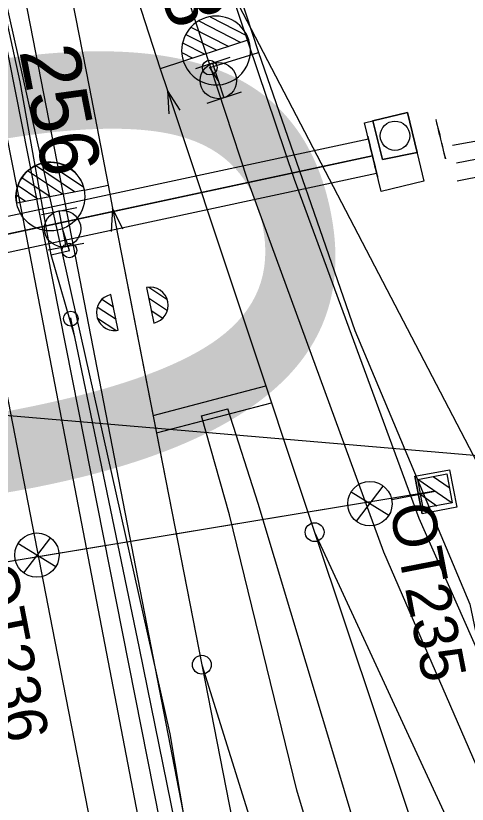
# Model space of a CAD drawing. Extents: x -545846 to -545044, y -1122650 to -1119108.
# Drawn here: x -545638.82 to -545623.48, y -1119592.1 to -1119565.28 of the extents above; entities that cross this region are included whole.
import ezdxf

# ---------------------------------------------------------------- set-up
doc = ezdxf.new("R2010")
doc.units = 0
for name, color, linetype in [('osvětlené plochy-hodnota-obrys', 7, 'Continuous'), ('Vrstva 1 - Koleje', 7, 'Continuous'), ('Vrstva 11 - Trakce', 7, 'Continuous'), ('Vrstva 12 - Trakce zaklady', 7, 'Continuous'), ('Vrstva 19', 7, 'Continuous'), ('Vrstva 2 - Vyhybky', 7, 'Continuous'), ('Vrstva 25', 7, 'Continuous'), ('Vrstva 27', 7, 'Continuous'), ('Vrstva 28 - zabzar', 7, 'Continuous'), ('Vrstva 3 - Lisy - Pocitaci body', 7, 'Continuous'), ('Vrstva 4 - Teren - stezky - prechody - plochy', 7, 'Continuous'), ('Vrstva 43', 7, 'Continuous'), ('Vrstva 44', 7, 'Continuous'), ('Vrstva 47', 7, 'Continuous'), ('Vrstva 63', 7, 'Continuous'), ('Vrstva 7 - Namezniky-vystroj', 7, 'Continuous')]:
    doc.layers.add(name, color=color, linetype=linetype)

msp = doc.modelspace()

# ---------------------------------------------------------------- linework, layer by layer
at = {"layer": 'osvětlené plochy-hodnota-obrys'}
msp.add_line((-545562.16, -1119697.713), (-545631.883, -1119563.683), dxfattribs=at)
msp.add_lwpolyline([(-545716.386, -1119223.717), (-545705.994, -1119221.66), (-545669.439, -1119408.759), (-545659.4, -1119462.635), (-545647.69, -1119521.347), (-545640.519, -1119558.729), (-545633.585, -1119589.698), (-545629.517, -1119613.814), (-545623.042, -1119645.057), (-545619.034, -1119667.556), (-545607.519, -1119727.517)], dxfattribs=at)
at = {"layer": 'Vrstva 1 - Koleje'}
for points in [[(-545653.037, -1119506.841), (-545652.888, -1119507.607), (-545652.099, -1119511.657), (-545649.059, -1119527.252), (-545644.851, -1119548.835), (-545643.914, -1119553.655), (-545642.404, -1119561.39), (-545639.909, -1119574.181), (-545637.584, -1119586.095), (-545635.82, -1119595.156), (-545633.965, -1119604.658), (-545632.137, -1119614.029), (-545631.264, -1119618.51), (-545629.612, -1119626.967), (-545629.361, -1119628.256), (-545628.203, -1119634.204), (-545626.651, -1119642.2), (-545624.573, -1119652.836), (-545622.753, -1119662.157), (-545621.579, -1119668.177), (-545619.497, -1119678.862), (-545617.408, -1119689.578), (-545615.292, -1119700.416), (-545613.256, -1119710.876)], [(-545643.734, -1119529.746), (-545643.581, -1119530.531), (-545640.551, -1119546.054), (-545635.586, -1119561.921), (-545633.918, -1119567.079)], [(-545643.734, -1119529.746), (-545643.581, -1119530.531), (-545642.913, -1119533.951), (-545640.551, -1119546.054), (-545637.367, -1119562.371), (-545636.332, -1119567.693), (-545635.682, -1119571.044)], [(-545633.918, -1119567.079), (-545633.672, -1119567.819), (-545628.667, -1119582.843), (-545621.718, -1119597.894), (-545620.45, -1119600.642), (-545619.123, -1119603.519)], [(-545633.918, -1119567.079), (-545633.672, -1119567.819), (-545628.667, -1119582.843), (-545623.418, -1119598.57), (-545620.367, -1119607.688), (-545618.295, -1119613.58)], [(-545635.682, -1119571.044), (-545635.531, -1119571.819), (-545632.499, -1119587.351), (-545627.516, -1119603.306)], [(-545635.682, -1119571.044), (-545635.531, -1119571.819), (-545634.862, -1119575.245), (-545632.499, -1119587.351), (-545629.31, -1119603.689), (-545628.19, -1119609.432), (-545627.412, -1119613.414), (-545625.512, -1119623.176), (-545623.669, -1119632.632), (-545622.964, -1119636.244), (-545621.873, -1119641.833), (-545619.406, -1119654.493), (-545617.375, -1119664.914), (-545615.537, -1119674.339), (-545613.73, -1119683.606), (-545613.194, -1119686.362), (-545611.288, -1119696.135), (-545609.289, -1119706.39), (-545607.258, -1119716.828)]]:
    msp.add_lwpolyline(points, dxfattribs=at)
at = {"layer": 'Vrstva 11 - Trakce'}
for p, q in [((-545624.636, -1119580.948), (-545624.091, -1119581.32)), ((-545625.157, -1119581.045), (-545623.993, -1119581.841)), ((-545624.576, -1119581.445), (-545651.228, -1119585.868)), ((-545625.062, -1119581.564), (-545624.51, -1119581.941))]:
    msp.add_line(p, q, dxfattribs=at)
msp.add_lwpolyline([(-545624.177, -1119580.861), (-545623.992, -1119581.844), (-545624.975, -1119582.029), (-545625.16, -1119581.046)], close=True, dxfattribs=at)
at = {"layer": 'Vrstva 12 - Trakce zaklady'}
for p, q in [((-545625.258, -1119580.939), (-545624.079, -1119580.717)), ((-545623.839, -1119581.994), (-545625.018, -1119582.216))]:
    msp.add_line(p, q, dxfattribs=at)
for points in [[(-545625.018, -1119582.216), (-545625.258, -1119580.939), (-545624.079, -1119580.717), (-545623.839, -1119581.994), (-545625.018, -1119582.216)], [(-545624.079, -1119580.717), (-545624.079, -1119580.717), (-545623.839, -1119581.994), (-545623.839, -1119581.994)], [(-545625.258, -1119580.939), (-545625.258, -1119580.939), (-545625.018, -1119582.216), (-545625.018, -1119582.216)]]:
    msp.add_lwpolyline(points, dxfattribs=at)
at = {"layer": 'Vrstva 19'}
for p, q in [((-545493.78, -1119544.934), (-545623.981, -1119569.695)), ((-545623.845, -1119570.275), (-545493.722, -1119545.549)), ((-545493.532, -1119546.146), (-545623.825, -1119570.899))]:
    msp.add_line(p, q, dxfattribs=at)
for points in [[(-545664.878, -1119577.632), (-545626.84, -1119569.462)], [(-545664.746, -1119578.217), (-545626.701, -1119570.045)], [(-545626.702, -1119570.04), (-545663.566, -1119577.951)], [(-545664.614, -1119578.802), (-545626.561, -1119570.628)]]:
    msp.add_lwpolyline(points, dxfattribs=at)
for centre, major_axis, ratio, start_param, end_param in [((-545624.383, -1119569.48), (-0.162, 0.672), 0.01248, 4.711186, 7.847666), ((-545626.696, -1119570.067), (-0.165, 0.695), 0.00013, 4.750534, 7.822978), ((-545624.383, -1119569.477), (0.162, -0.672), 0.01248, 4.711186, 7.847666), ((-545626.696, -1119570.067), (-0.166, 0.694), 0.000133, 1.539607, 4.75072)]:
    msp.add_ellipse(centre, major_axis=major_axis, ratio=ratio, start_param=start_param, end_param=end_param, dxfattribs=at)
at = {"layer": 'Vrstva 2 - Vyhybky'}
for p, q in [((-545632.607, -1119565.454), (-545631.171, -1119566.189)), ((-545632.222, -1119565.31), (-545630.96, -1119565.955)), ((-545632.868, -1119565.663), (-545631.58, -1119566.321)), ((-545633.046, -1119565.913), (-545631.99, -1119566.453)), ((-545633.153, -1119566.199), (-545632.399, -1119566.585)), ((-545630.9, -1119566.101), (-545633.128, -1119566.821)), ((-545630.9, -1119566.1), (-545630.9, -1119566.101)), ((-545633.181, -1119566.527), (-545632.808, -1119566.717)), ((-545633.128, -1119566.821), (-545633.918, -1119567.079)), ((-545636.513, -1119571.117), (-545637.773, -1119570.268)), ((-545637.239, -1119571.35), (-545638.418, -1119570.557)), ((-545636.823, -1119571.269), (-545638.149, -1119570.376)), ((-545637.656, -1119571.431), (-545638.615, -1119570.786)), ((-545638.073, -1119571.512), (-545638.746, -1119571.059)), ((-545636.489, -1119571.204), (-545635.682, -1119571.044)), ((-545636.489, -1119571.204), (-545638.788, -1119571.652)), ((-545636.49, -1119571.203), (-545636.489, -1119571.204)), ((-545638.49, -1119571.594), (-545638.806, -1119571.381))]:
    msp.add_line(p, q, dxfattribs=at)
for points in [[(-545633.918, -1119567.079), (-545633.672, -1119567.819), (-545628.667, -1119582.843), (-545623.418, -1119598.57)], [(-545633.231, -1119568.487), (-545633.672, -1119567.819), (-545633.624, -1119568.618)], [(-545635.682, -1119571.044), (-545635.531, -1119571.819), (-545632.499, -1119587.351), (-545629.31, -1119603.689)], [(-545635.18, -1119572.538), (-545635.531, -1119571.819), (-545635.586, -1119572.617)], [(-545628.667, -1119582.843), (-545621.718, -1119597.894)], [(-545632.499, -1119587.351), (-545627.516, -1119603.306)]]:
    msp.add_lwpolyline(points, dxfattribs=at)
for centre, radius in [((-545637.645, -1119571.428), 1.17), ((-545628.667, -1119582.843), 0.32), ((-545632.499, -1119587.351), 0.32)]:
    msp.add_circle(centre, radius, dxfattribs=at)
for centre, radius, start, end in [((-545632.014, -1119566.461), 1.171, 17.9478, 197.9086), ((-545632.015, -1119566.462), 1.17, 197.8583, 18.3278), ((-545637.639, -1119571.428), 1.171, 11.0643, 191.0252)]:
    msp.add_arc(centre, radius, start, end, dxfattribs=at)
at = {"layer": 'Vrstva 25'}
for p, q in [((-545627.248, -1119582.472), (-545626.335, -1119581.273)), ((-545627.427, -1119581.473), (-545626.143, -1119582.264)), ((-545626.048, -1119581.732), (-545624.576, -1119581.445)), ((-545637.645, -1119583.025), (-545638.558, -1119584.224)), ((-545637.466, -1119584.025), (-545638.75, -1119583.233))]:
    msp.add_line(p, q, dxfattribs=at)
msp.add_lwpolyline([(-545624.576, -1119581.445), (-545650.585, -1119585.754)], dxfattribs=at)
for centre in [(-545626.789, -1119581.874), (-545638.104, -1119583.623)]:
    msp.add_circle(centre, 0.754, dxfattribs=at)
at = {"layer": 'Vrstva 27'}
for p, q in [((-545632.238, -1119567.016), (-545632.222, -1119567.064)), ((-545636.995, -1119573.285), (-545637.005, -1119573.235)), ((-545636.945, -1119575.605), (-545636.955, -1119575.555))]:
    msp.add_line(p, q, dxfattribs=at)
for centre in [(-545632.23, -1119567.04), (-545637, -1119573.26), (-545636.95, -1119575.58)]:
    msp.add_circle(centre, 0.25, dxfattribs=at)
at = {"layer": 'Vrstva 28 - zabzar'}
msp.add_line((-545636.82, -1119576.2), (-545636.95, -1119575.58), dxfattribs=at)
for points in [[(-545629.8, -1119612.08), (-545631.93, -1119600), (-545634.62, -1119586.79), (-545636.82, -1119576.2), (-545637.62, -1119573.41), (-545638.67, -1119567.53), (-545639.49, -1119563.82), (-545639.85, -1119560.18), (-545641.01, -1119554.98), (-545644.07, -1119538.51), (-545646.66, -1119527.22), (-545647.144, -1119525.532), (-545647.46, -1119524.27), (-545648.47, -1119517.64), (-545649.03, -1119512.55), (-545649.84, -1119510.97), (-545650.5, -1119507.69), (-545650.68, -1119506.85), (-545651.64, -1119501.97), (-545654.86, -1119485.39)], [(-545642.06, -1119524.64), (-545640.63, -1119530.69), (-545639.91, -1119533.39), (-545637.75, -1119542.87), (-545634.65, -1119553.48), (-545633.29, -1119558.34), (-545631.9, -1119562.47), (-545630.58, -1119566.53), (-545627.3, -1119575.98), (-545623.39, -1119585.29), (-545622.71, -1119588.53), (-545617.63, -1119597.85), (-545616.86, -1119599.1), (-545615.46, -1119602.1), (-545610.32, -1119612.67), (-545606.39, -1119619.85), (-545601.98, -1119627.31), (-545600.79, -1119629.4), (-545602.25, -1119630.29), (-545602.73, -1119630.37), (-545602.6, -1119631.07)], [(-545631.94, -1119567.48), (-545632.23, -1119567.04), (-545630.58, -1119566.53)], [(-545637.62, -1119573.41), (-545637, -1119573.26), (-545637.23, -1119572.52)]]:
    msp.add_lwpolyline(points, dxfattribs=at)
at = {"layer": 'Vrstva 3 - Lisy - Pocitaci body'}
for p, q in [((-545631.548, -1119566.702), (-545632.718, -1119567.088)), ((-545632.133, -1119566.895), (-545631.747, -1119568.065)), ((-545631.162, -1119567.872), (-545632.332, -1119568.258)), ((-545637.952, -1119572.033), (-545636.743, -1119571.798)), ((-545637.112, -1119573.125), (-545637.348, -1119571.915)), ((-545637.717, -1119573.242), (-545636.508, -1119573.007)), ((-545634.38, -1119574.521), (-545634.135, -1119575.728)), ((-545634.297, -1119574.51), (-545633.684, -1119574.918)), ((-545635.344, -1119575.969), (-545635.589, -1119574.762)), ((-545635.589, -1119574.762), (-545635.589, -1119574.762)), ((-545635.503, -1119575.186), (-545635.899, -1119574.928)), ((-545634.308, -1119574.876), (-545633.669, -1119575.299)), ((-545635.416, -1119575.614), (-545636.055, -1119575.191)), ((-545634.221, -1119575.304), (-545633.825, -1119575.562)), ((-545635.427, -1119575.98), (-545636.04, -1119575.572)), ((-545634.135, -1119575.728), (-545634.135, -1119575.728))]:
    msp.add_line(p, q, dxfattribs=at)
for centre in [(-545631.939, -1119567.482), (-545637.231, -1119572.518)]:
    msp.add_circle(centre, 0.616, dxfattribs=at)
for centre, start, end in [((-545634.257, -1119575.125), 11.4785, 101.4785), ((-545635.467, -1119575.365), 101.4785, 191.4785), ((-545634.257, -1119575.125), 281.4785, 11.4785), ((-545635.467, -1119575.365), 191.4785, 281.4785)]:
    msp.add_arc(centre, 0.616, start, end, dxfattribs=at)
at = {"layer": 'Vrstva 4 - Teren - stezky - prechody - plochy'}
for points in [[(-545658.883, -1119493.553), (-545657.157, -1119493.293), (-545652.405, -1119492.3), (-545652.635, -1119491.288), (-545650.366, -1119490.81), (-545647.977, -1119490.635), (-545647.021, -1119490.553), (-545646.397, -1119493.557), (-545647.333, -1119493.819), (-545645.82, -1119500.741), (-545643.399, -1119514.848), (-545641.375, -1119525.057), (-545641.371, -1119525.071), (-545641.178, -1119529.067), (-545640.191, -1119530.535), (-545638.605, -1119538.618), (-545635.76, -1119550.157), (-545633.177, -1119559.269), (-545632.795, -1119560.648), (-545629.367, -1119570.838), (-545625.13, -1119582.366), (-545619.179, -1119595.829), (-545614.308, -1119606.243)], [(-545647.977, -1119490.635), (-545647.021, -1119490.553), (-545646.397, -1119493.557), (-545647.333, -1119493.819), (-545645.82, -1119500.741), (-545643.399, -1119514.848), (-545641.375, -1119525.057), (-545641.371, -1119525.071), (-545641.178, -1119529.067), (-545640.191, -1119530.535), (-545638.605, -1119538.618), (-545635.76, -1119550.157), (-545633.177, -1119559.269), (-545632.795, -1119560.648), (-545629.367, -1119570.838), (-545625.13, -1119582.366), (-545619.179, -1119595.829), (-545614.308, -1119606.243)], [(-545647.977, -1119490.635), (-545646.634, -1119503.488), (-545644.84, -1119514.959), (-545642.926, -1119525.846), (-545639.991, -1119539.467), (-545637.309, -1119550.216), (-545633.98, -1119561.601), (-545630.95, -1119570.869), (-545626.323, -1119583.508), (-545620.798, -1119596.258), (-545615.652, -1119606.86)], [(-545627.289, -1119622.488), (-545637.141, -1119571.643), (-545644.261, -1119535.203), (-545650.142, -1119505.011), (-545652.467, -1119492.497), (-545654.152, -1119492.935)], [(-545628.853, -1119622.763), (-545638.621, -1119571.934), (-545645.785, -1119535.614), (-545651.795, -1119505.293), (-545654.152, -1119492.935)], [(-545623.51, -1119605.555), (-545624.228, -1119605.785), (-545624.392, -1119604.982), (-545625.226, -1119605.173), (-545629.276, -1119591.613), (-545631.565, -1119582.258), (-545632.511, -1119578.885), (-545631.617, -1119578.652)], [(-545623.51, -1119605.555), (-545627.847, -1119590.999), (-545630.583, -1119581.864), (-545631.617, -1119578.652)]]:
    msp.add_lwpolyline(points, dxfattribs=at)
at = {"layer": 'Vrstva 43'}
msp.add_circle((-545625.937, -1119569.359), 0.5, dxfattribs=at)
at = {"layer": 'Vrstva 44'}
msp.add_lwpolyline([(-545622.746, -1119648.835), (-545632.623, -1119599.24), (-545640.335, -1119560.272)], dxfattribs=at)
at = {"layer": 'Vrstva 47'}
for p, q in [((-545625.51, -1119568.572), (-545625.51, -1119568.572)), ((-545625.51, -1119568.572), (-545625.51, -1119568.572)), ((-545626.969, -1119568.92), (-545626.969, -1119568.92)), ((-545626.694, -1119568.838), (-545626.69, -1119568.854)), ((-545625.185, -1119569.933), (-545625.185, -1119569.933)), ((-545626.357, -1119570.165), (-545626.357, -1119570.165)), ((-545624.953, -1119570.906), (-545624.953, -1119570.906)), ((-545626.412, -1119571.255), (-545626.412, -1119571.255))]:
    msp.add_line(p, q, dxfattribs=at)
for points in [[(-545626.969, -1119568.92), (-545625.51, -1119568.572), (-545624.953, -1119570.906), (-545626.412, -1119571.255)], [(-545626.969, -1119568.92), (-545625.51, -1119568.572), (-545624.953, -1119570.906), (-545626.412, -1119571.255)], [(-545626.357, -1119570.165), (-545626.694, -1119568.838), (-545625.51, -1119568.572), (-545625.185, -1119569.933)], [(-545626.357, -1119570.165), (-545625.185, -1119569.933), (-545625.51, -1119568.572), (-545626.69, -1119568.854)]]:
    msp.add_lwpolyline(points, close=True, dxfattribs=at)
at = {"layer": 'Vrstva 63'}
msp.add_line((-545588.032, -1119583.243), (-545688.629, -1119574.644), dxfattribs=at)
at = {"layer": 'Vrstva 7 - Namezniky-vystroj'}
for p, q in [((-545634.153, -1119578.877), (-545630.324, -1119577.87)), ((-545634.038, -1119579.467), (-545630.134, -1119578.44))]:
    msp.add_line(p, q, dxfattribs=at)

# ---------------------------------------------------------------- texts
at = {"layer": 'osvětlené plochy-hodnota-obrys'}
msp.add_text('20', height=22.7812, rotation=281.0956, dxfattribs=at).set_placement((-545655.704, -1119551.441))
at = {"layer": 'Vrstva 2 - Vyhybky'}
for s, rotation, p in [('258', 288.4339, (-545634.881, -1119561.597)), ('256', 281.0447, (-545638.709, -1119566.475))]:
    msp.add_text(s, height=2, rotation=rotation, dxfattribs=at).set_placement(p)
at = {"layer": 'Vrstva 25'}
for s, rotation, p in [('OT235', 281.0458, (-545626.134, -1119582.001)), ('OT236', 281.0424, (-545640.317, -1119584.052))]:
    msp.add_text(s, height=1.5, rotation=rotation, dxfattribs=at).set_placement(p)

doc.saveas('drawing.dxf')
